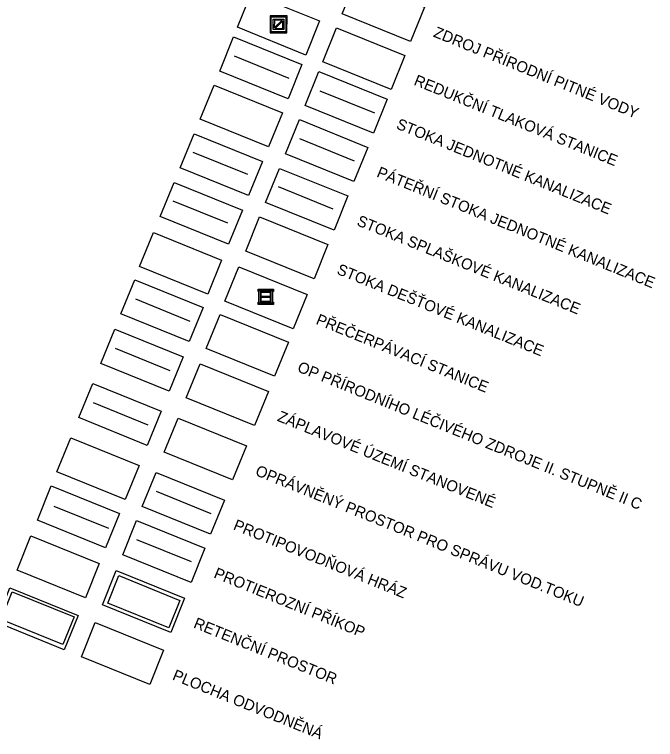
# Model space of a CAD drawing. Extents: x -522797 to -519326, y -1191143 to -1184078.
# Drawn here: x -521890 to -521020, y -1190487 to -1189504 of the extents above; entities that cross this region are included whole.
import ezdxf

# ---------------------------------------------------------------- set-up
doc = ezdxf.new("R2010")
doc.units = 0
for name, color, linetype in [('Implicitní', 7, 'Continuous'), ('kan_pater_j_n', 7, 'Continuous'), ('kan_stoka_j_n', 7, 'Continuous'), ('kan_stoka_j_s', 7, 'Continuous'), ('kan_stoka_s_n', 7, 'Continuous'), ('kan_stoka_s_s', 7, 'Continuous'), ('ložisk_nerost', 7, 'Continuous'), ('odvodneni_s', 7, 'Continuous'), ('OPLZ_II_s', 7, 'Continuous'), ('pe_prikop_n', 7, 'Continuous'), ('pe_prikop_s', 7, 'Continuous'), ('pp_hraz_n', 7, 'Continuous'), ('ret_prostor_n', 7, 'Continuous'), ('sprava_toku_s', 7, 'Continuous'), ('zapl_uz_zdok_s', 7, 'Continuous'), ('zast_HD_s', 7, 'Continuous')]:
    doc.layers.add(name, color=color, linetype=linetype)

msp = doc.modelspace()

# ---------------------------------------------------------------- linework, layer by layer
at = {"layer": 'Implicitní'}
for points in [[(-521426.14, -1189456.29), (-521333.46, -1189493.85), (-521352.24, -1189540.19), (-521444.92, -1189502.63)], [(-521568.47, -1189474.7), (-521475.79, -1189512.26), (-521494.57, -1189558.6), (-521587.25, -1189521.04)], [(-521452.62, -1189521.65), (-521359.95, -1189559.21), (-521378.73, -1189605.55), (-521471.4, -1189567.99)], [(-521592.43, -1189534), (-521499.75, -1189571.56), (-521518.53, -1189617.9), (-521611.21, -1189580.34)], [(-521476.58, -1189580.96), (-521383.9, -1189618.52), (-521402.69, -1189664.86), (-521495.36, -1189627.29)], [(-521618.92, -1189599.36), (-521526.24, -1189636.92), (-521545.02, -1189683.26), (-521637.7, -1189645.7)], [(-521503.07, -1189646.31), (-521410.39, -1189683.88), (-521429.17, -1189730.21), (-521521.85, -1189692.65)], [(-521646.1, -1189665.54), (-521553.39, -1189703), (-521572.12, -1189749.36), (-521664.83, -1189711.9)], [(-521530.21, -1189712.36), (-521437.49, -1189749.83), (-521456.22, -1189796.18), (-521548.94, -1189758.72)], [(-521673.2, -1189731.49), (-521580.48, -1189768.95), (-521599.21, -1189815.31), (-521691.93, -1189777.85)], [(-521557.3, -1189778.31), (-521464.58, -1189815.78), (-521483.31, -1189862.13), (-521576.03, -1189824.67)], [(-521701.34, -1189799.21), (-521608.67, -1189836.77), (-521627.45, -1189883.11), (-521720.12, -1189845.55)], [(-521585.5, -1189846.16), (-521492.82, -1189883.72), (-521511.6, -1189930.06), (-521604.28, -1189892.5)], [(-521726.58, -1189863.63), (-521633.91, -1189901.19), (-521652.69, -1189947.53), (-521745.37, -1189909.97)], [(-521610.74, -1189910.58), (-521518.06, -1189948.14), (-521536.84, -1189994.48), (-521629.52, -1189956.92)], [(-521753.75, -1189930.65), (-521661.07, -1189968.21), (-521679.85, -1190014.55), (-521772.53, -1189976.99)], [(-521637.9, -1189977.6), (-521545.22, -1190015.16), (-521564, -1190061.5), (-521656.68, -1190023.94)], [(-521783.6, -1190004.31), (-521690.92, -1190041.87), (-521709.7, -1190088.21), (-521802.38, -1190050.65)], [(-521667.75, -1190051.26), (-521575.08, -1190088.82), (-521593.86, -1190135.16), (-521686.53, -1190097.6)], [(-521813.45, -1190077.97), (-521720.78, -1190115.53), (-521739.56, -1190161.87), (-521832.24, -1190124.31)], [(-521697.61, -1190124.93), (-521604.93, -1190162.49), (-521623.71, -1190208.83), (-521716.39, -1190171.26)], [(-521839.95, -1190143.34), (-521747.27, -1190180.9), (-521766.05, -1190227.24), (-521858.73, -1190189.68)], [(-521724.1, -1190190.29), (-521631.42, -1190227.85), (-521650.2, -1190274.19), (-521742.88, -1190236.63)], [(-521867.42, -1190211.13), (-521774.74, -1190248.69), (-521793.52, -1190295.03), (-521886.2, -1190257.47)], [(-521751.57, -1190258.08), (-521658.9, -1190295.64), (-521677.68, -1190341.98), (-521770.35, -1190304.42)], [(-521896.02, -1190281.7), (-521803.34, -1190319.26), (-521822.13, -1190365.6), (-521914.8, -1190328.04)], [(-521780.18, -1190328.65), (-521687.5, -1190366.21), (-521706.28, -1190412.55), (-521798.96, -1190374.99)]]:
    msp.add_lwpolyline(points, close=True, dxfattribs=at)
at = {"layer": 'kan_pater_j_n'}
msp.add_line((-521502.89, -1189671.96), (-521428.74, -1189702.01), dxfattribs=at)
at = {"layer": 'kan_stoka_j_n'}
msp.add_line((-521475.34, -1189607.03), (-521401.2, -1189637.08), dxfattribs=at)
at = {"layer": 'kan_stoka_j_s'}
msp.add_line((-521591.61, -1189559.91), (-521517.47, -1189589.96), dxfattribs=at)
at = {"layer": 'kan_stoka_s_n'}
msp.add_line((-521531.81, -1189737.13), (-521457.64, -1189767.1), dxfattribs=at)
at = {"layer": 'kan_stoka_s_s'}
for p, q in [((-521647.71, -1189690.3), (-521573.54, -1189720.27)), ((-521674.81, -1189756.25), (-521600.63, -1189786.22))]:
    msp.add_line(p, q, dxfattribs=at)
at = {"layer": 'ložisk_nerost'}
for p, q in [((-521538.63, -1189524.15), (-521538.62, -1189509.77)), ((-521538.62, -1189509.77), (-521531.43, -1189509.78)), ((-521537.18, -1189511.21), (-521537.19, -1189521.69)), ((-521537.19, -1189521.69), (-521526.7, -1189511.22)), ((-521531.43, -1189511.21), (-521537.18, -1189511.21)), ((-521525.68, -1189512.23), (-521536.17, -1189522.71)), ((-521531.43, -1189509.78), (-521531.43, -1189511.21)), ((-521531.38, -1189511.21), (-521531.38, -1189509.78)), ((-521531.38, -1189509.78), (-521524.24, -1189509.78)), ((-521526.7, -1189511.22), (-521531.38, -1189511.21)), ((-521525.69, -1189522.72), (-521525.68, -1189512.23)), ((-521524.24, -1189509.78), (-521524.25, -1189524.15)), ((-521531.44, -1189524.15), (-521538.63, -1189524.15)), ((-521536.17, -1189522.71), (-521531.44, -1189522.71)), ((-521531.44, -1189522.71), (-521531.44, -1189524.15)), ((-521531.39, -1189524.15), (-521531.39, -1189522.71)), ((-521531.39, -1189522.71), (-521525.69, -1189522.72)), ((-521524.25, -1189524.15), (-521531.39, -1189524.15))]:
    msp.add_line(p, q, dxfattribs=at)
for points in [[(-521531.46, -1189505.52), (-521542.87, -1189505.51), (-521542.88, -1189528.39), (-521520, -1189528.41), (-521519.99, -1189505.53), (-521531.43, -1189505.52)], [(-521541.46, -1189506.92), (-521521.4, -1189506.94), (-521521.41, -1189527), (-521541.47, -1189526.99), (-521541.46, -1189506.92)], [(-521531.43, -1189506.93), (-521521.4, -1189506.93), (-521521.41, -1189527), (-521541.47, -1189526.99), (-521541.46, -1189506.92), (-521531.46, -1189506.93)], [(-521531.46, -1189506.93), (-521531.46, -1189505.52)], [(-521531.43, -1189505.52), (-521531.43, -1189506.93)]]:
    msp.add_lwpolyline(points, dxfattribs=at)
at = {"layer": 'odvodneni_s'}
msp.add_lwpolyline([(-521892.81, -1190286.84), (-521808.94, -1190320.84), (-521824.15, -1190358.37), (-521908.02, -1190324.38)], close=True, dxfattribs=at)
at = {"layer": 'OPLZ_II_s'}
msp.add_line((-521725.76, -1189889.54), (-521651.62, -1189919.59), dxfattribs=at)
at = {"layer": 'pe_prikop_n'}
msp.add_line((-521724.17, -1190215.83), (-521650.03, -1190245.88), dxfattribs=at)
at = {"layer": 'pe_prikop_s'}
msp.add_line((-521836.52, -1190170.61), (-521762.37, -1190200.66), dxfattribs=at)
at = {"layer": 'pp_hraz_n'}
msp.add_line((-521697.68, -1190150.47), (-521623.54, -1190180.52), dxfattribs=at)
at = {"layer": 'ret_prostor_n'}
msp.add_lwpolyline([(-521748.23, -1190265.01), (-521665.2, -1190298.65), (-521680.25, -1190335.81), (-521763.29, -1190302.17)], close=True, dxfattribs=at)
at = {"layer": 'sprava_toku_s'}
msp.add_line((-521782.78, -1190030.22), (-521708.64, -1190060.27), dxfattribs=at)
at = {"layer": 'zapl_uz_zdok_s'}
msp.add_line((-521752.93, -1189956.56), (-521678.78, -1189986.61), dxfattribs=at)
at = {"layer": 'zast_HD_s'}
for points in [[(-521559.33, -1189876.34), (-521541.86, -1189876.33)], [(-521559.33, -1189879.66), (-521559.33, -1189876.34)], [(-521558.05, -1189879.66), (-521559.33, -1189879.66)], [(-521558.05, -1189877.62), (-521539.81, -1189877.61), (-521539.81, -1189895.85), (-521558.05, -1189895.86), (-521558.05, -1189877.62)], [(-521541.86, -1189877.61), (-521558.05, -1189877.62), (-521558.05, -1189879.66)], [(-521548.93, -1189879.44), (-521556.22, -1189879.45)], [(-521556.22, -1189879.45), (-521556.22, -1189894.03)], [(-521555.25, -1189886.25), (-521555.25, -1189880.42)], [(-521555.25, -1189880.42), (-521548.93, -1189880.42)], [(-521548.93, -1189880.42), (-521548.93, -1189879.44)], [(-521541.64, -1189879.44), (-521548.91, -1189879.44)], [(-521548.91, -1189879.44), (-521548.91, -1189880.42)], [(-521548.91, -1189880.42), (-521542.61, -1189880.42)], [(-521542.61, -1189880.42), (-521542.61, -1189886.25)], [(-521541.86, -1189876.33), (-521538.53, -1189876.33), (-521538.53, -1189879.66)], [(-521539.81, -1189879.66), (-521539.81, -1189877.61), (-521541.86, -1189877.61)], [(-521541.64, -1189894.02), (-521541.64, -1189879.44)], [(-521538.53, -1189879.66), (-521539.81, -1189879.66)], [(-521542.61, -1189886.25), (-521555.25, -1189886.25)], [(-521548.93, -1189893.05), (-521555.25, -1189893.05), (-521555.25, -1189887.22)], [(-521555.25, -1189887.22), (-521542.61, -1189887.22)], [(-521542.61, -1189887.22), (-521542.61, -1189893.05), (-521548.91, -1189893.05)], [(-521556, -1189897.14), (-521559.33, -1189897.14), (-521559.33, -1189893.81)], [(-521559.33, -1189893.81), (-521558.05, -1189893.81)], [(-521558.05, -1189893.81), (-521558.05, -1189895.86), (-521541.86, -1189895.85)], [(-521556.22, -1189894.03), (-521548.93, -1189894.02)], [(-521538.53, -1189893.8), (-521538.53, -1189897.13), (-521556, -1189897.14)], [(-521548.93, -1189894.02), (-521548.93, -1189893.05)], [(-521548.91, -1189893.05), (-521548.91, -1189894.02)], [(-521548.91, -1189894.02), (-521541.64, -1189894.02)], [(-521541.86, -1189895.85), (-521539.81, -1189895.85), (-521539.81, -1189893.81)], [(-521539.81, -1189893.81), (-521538.53, -1189893.8)]]:
    msp.add_lwpolyline(points, dxfattribs=at)

# ---------------------------------------------------------------- texts
at = {"layer": 'Implicitní'}
for s, rotation, p in [('ZDROJ PŘÍRODNÍ PITNÉ VODY', 337.93793, (-521322.5, -1189533.36)), ('REDUKČNÍ TLAKOVÁ STANICE', 337.93793, (-521348.98, -1189598.72)), ('STOKA JEDNOTNÉ KANALIZACE', 337.93793, (-521372.94, -1189658.03)), ('PÁTEŘNÍ STOKA JEDNOTNÉ KANALIZACE', 337.93793, (-521399.43, -1189723.39)), ('STOKA SPLAŠKOVÉ KANALIZACE', 337.99937, (-521426.48, -1189789.32)), ('STOKA DEŠŤOVÉ KANALIZACE', 337.99937, (-521453.58, -1189855.27)), ('PŘEČERPÁVACÍ STANICE', 337.93793, (-521481.86, -1189923.23)), ('OP PŘÍRODNÍHO LÉČIVÉHO ZDROJE II. STUPNĚ II C', 337.93793, (-521507.1, -1189987.65)), ('ZÁPLAVOVÉ ÚZEMÍ STANOVENÉ', 337.93793, (-521534.26, -1190054.67)), ('OPRÁVNĚNÝ PROSTOR PRO SPRÁVU VOD.TOKU', 337.93793, (-521564.11, -1190128.34)), ('PROTIPOVODŇOVÁ HRÁZ', 337.93793, (-521593.97, -1190202)), ('PROTIEROZNÍ PŘÍKOP', 337.93793, (-521620.46, -1190267.36)), ('RETENČNÍ PROSTOR', 337.93793, (-521647.93, -1190335.15)), ('PLOCHA ODVODNĚNÁ', 337.93806, (-521676.54, -1190405.72))]:
    msp.add_text(s, height=15, rotation=rotation, dxfattribs=at).set_placement(p)

doc.saveas('drawing.dxf')
